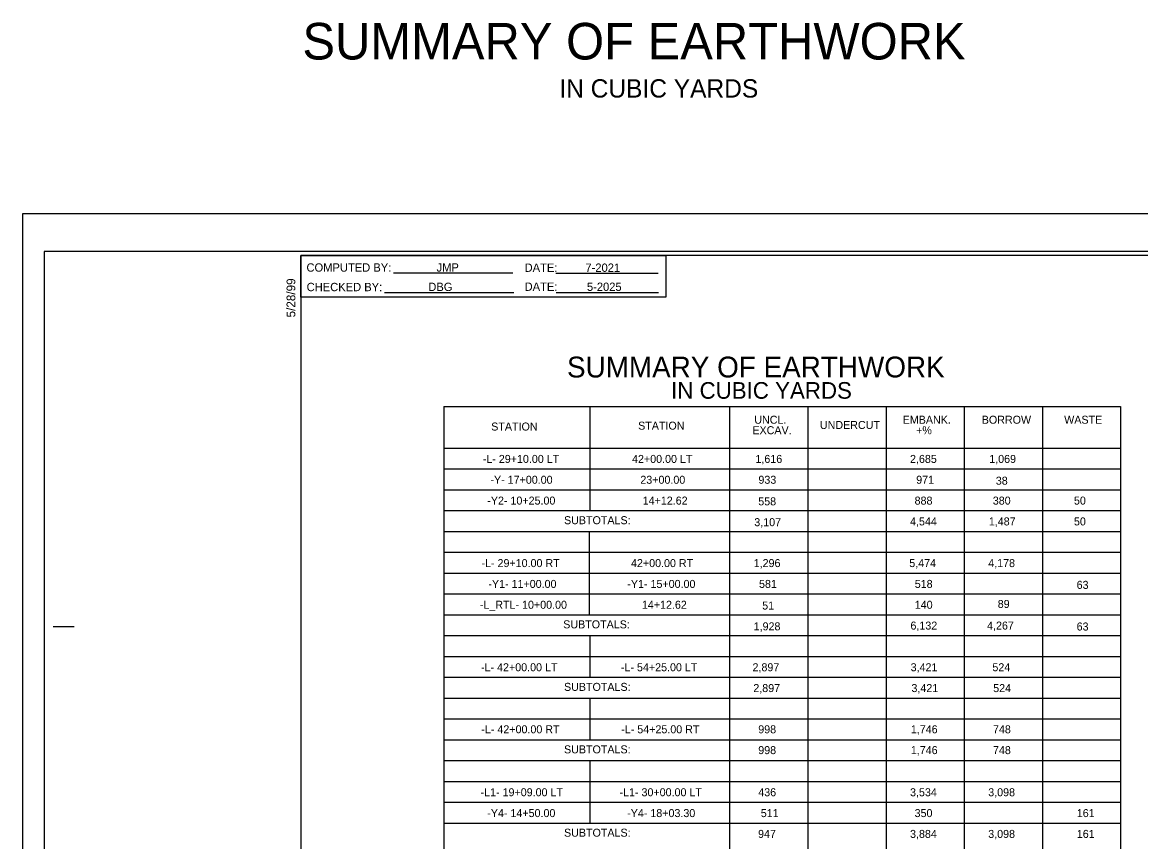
# Model space of a CAD drawing. Extents: x 1729625 to 1732014, y 538843 to 541329.
# Drawn here: x 1729815 to 1730486, y 540638 to 541130 of the extents above; entities that cross this region are included whole.
import ezdxf

# ---------------------------------------------------------------- set-up
doc = ezdxf.new("R2010")
doc.units = 0
for name, color, linetype in [('Old_Level_2', 7, 'Continuous'), ('Prop EOT', 7, 'Continuous'), ('Prop Horizontal Alignment', 7, 'Continuous'), ('Sheet Cutting Line CELL', 7, 'Continuous'), ('Sheet Data Field CELL', 7, 'Continuous'), ('Sheet Plot Border Inside CELL', 7, 'Continuous'), ('Sheet Plot Border Outside CELL', 7, 'Continuous'), ('Sheet Summary CELL', 7, 'Continuous')]:
    doc.layers.add(name, color=color, linetype=linetype)

msp = doc.modelspace()

# ---------------------------------------------------------------- linework, layer by layer
at = {"layer": 'Old_Level_2'}
for p, q in [((1730038.12, 540979.51), (1730109.67, 540979.51)), ((1730135.47, 540979.36), (1730196.87, 540979.36)), ((1730032.67, 540967.81), (1730110.37, 540967.81)), ((1730135.62, 540967.86), (1730197.02, 540967.86))]:
    msp.add_line(p, q, dxfattribs=at)
msp.add_lwpolyline([(1729982.47, 540989.91), (1730201.47, 540989.91), (1730201.47, 540964.91), (1729982.47, 540964.91)], close=True, dxfattribs=at)
at = {"layer": 'Prop EOT'}
for p, q in [((1730068.38, 540899.44), (1730474.29, 540899.44)), ((1730068.38, 540899.44), (1730068.38, 540361.94)), ((1730155.91, 540899.44), (1730155.91, 540836.94)), ((1730239.79, 540899.44), (1730239.79, 540361.94)), ((1730286.69, 540899.44), (1730286.69, 540361.94)), ((1730333.59, 540899.44), (1730333.59, 540361.94)), ((1730380.49, 540899.44), (1730380.49, 540361.94)), ((1730427.39, 540899.44), (1730427.39, 540361.94)), ((1730474.29, 540899.44), (1730474.29, 540361.94)), ((1730068.38, 540874.44), (1730474.29, 540874.44)), ((1730068.38, 540861.94), (1730474.29, 540861.94)), ((1730068.38, 540849.44), (1730474.29, 540849.44)), ((1730068.38, 540836.94), (1730474.29, 540836.94)), ((1730068.38, 540824.44), (1730474.29, 540824.44)), ((1730155.43, 540824.44), (1730155.43, 540774.44)), ((1730068.38, 540811.94), (1730474.29, 540811.94)), ((1730068.38, 540799.44), (1730474.29, 540799.44)), ((1730068.38, 540786.94), (1730474.29, 540786.94)), ((1730068.38, 540774.44), (1730474.29, 540774.44)), ((1730068.38, 540761.94), (1730474.29, 540761.94)), ((1730155.91, 540761.94), (1730155.91, 540736.94)), ((1730068.38, 540749.44), (1730474.29, 540749.44)), ((1730068.38, 540736.94), (1730474.29, 540736.94)), ((1730068.38, 540724.44), (1730474.29, 540724.44)), ((1730155.91, 540724.44), (1730155.91, 540699.44)), ((1730068.38, 540711.94), (1730474.29, 540711.94)), ((1730068.38, 540699.44), (1730474.29, 540699.44)), ((1730068.38, 540686.94), (1730474.29, 540686.94)), ((1730155.91, 540686.94), (1730155.91, 540649.44)), ((1730068.38, 540674.44), (1730474.29, 540674.44)), ((1730068.38, 540661.94), (1730474.29, 540661.94)), ((1730068.38, 540649.44), (1730474.29, 540649.44))]:
    msp.add_line(p, q, dxfattribs=at)
at = {"layer": 'Prop Horizontal Alignment'}
for p, q in [((1730193.49, 540868.01), (1730193.49, 540868.01)), ((1730199.74, 540867.91), (1730199.74, 540867.91)), ((1730208.79, 540868.11), (1730208.79, 540868.11)), ((1730214.39, 540868.01), (1730214.39, 540868.01))]:
    msp.add_line(p, q, dxfattribs=at)
at = {"layer": 'Sheet Cutting Line CELL'}
for p, q in [((1731499.47, 541014.91), (1729815.47, 541014.91)), ((1729815.47, 541014.91), (1729815.47, 539914.91))]:
    msp.add_line(p, q, dxfattribs=at)
at = {"layer": 'Sheet Plot Border Inside CELL'}
msp.add_lwpolyline([(1731494.97, 540992.46), (1729828.47, 540992.46), (1729828.47, 539937.36), (1731494.97, 539937.36)], close=True, dxfattribs=at)
at = {"layer": 'Sheet Plot Border Outside CELL'}
msp.add_lwpolyline([(1731499.47, 541014.91), (1729815.47, 541014.91), (1729815.47, 539914.91), (1731499.47, 539914.91)], close=True, dxfattribs=at)
at = {"layer": 'Sheet Summary CELL'}
for p, q in [((1729982.47, 540989.91), (1729982.47, 540949.46)), ((1729833.97, 540767.41), (1729846.47, 540767.41))]:
    msp.add_line(p, q, dxfattribs=at)
msp.add_lwpolyline([(1731482.47, 540989.91), (1729982.47, 540989.91), (1729982.47, 539939.91), (1731482.47, 539939.91)], close=True, dxfattribs=at)

# ---------------------------------------------------------------- texts
at = {"layer": 'Old_Level_2'}
for s, height, p in [('COMPUTED BY:', 4.9998, (1729985.92, 540980.26)), ('DATE:', 5, (1730116.77, 540980.16)), ('CHECKED BY:', 4.9998, (1729986.02, 540968.56)), ('DATE:', 5, (1730116.77, 540968.76))]:
    msp.add_text(s, height=height, dxfattribs=at).set_placement(p)
at = {"layer": 'Prop Horizontal Alignment'}
for s, height, p in [('SUMMARY OF EARTHWORK', 12.5001, (1730142.2, 540916.78)), ('IN CUBIC YARDS', 10, (1730204.66, 540904))]:
    msp.add_text(s, height=height, rotation=0.01193, dxfattribs=at).set_placement(p)
for s, p in [('UNCL.', (1730254.58, 540889.03)), ('EMBANK.', (1730343.59, 540889.03)), ('BORROW', (1730391.04, 540889.03)), ('WASTE', (1730440.49, 540889.03)), ('STATION', (1730096.74, 540884.94)), ('STATION', (1730184.88, 540885.47)), ('EXCAV.', (1730253.43, 540882.73)), ('UNDERCUT', (1730293.94, 540885.88)), ('+%', (1730351.65, 540882.73)), ('-L- 29+10.00 LT', (1730091.69, 540865.51)), ('42+00.00 LT', (1730181.23, 540865.51)), ('1,616', (1730255.26, 540865.51)), ('2,685', (1730348, 540865.51)), ('1,069', (1730395.53, 540865.51)), ('-Y- 17+00.00', (1730096.28, 540853.01)), ('23+00.00', (1730186.21, 540853.01)), ('933', (1730257.05, 540853.01)), ('971', (1730351.7, 540853.01)), ('38', (1730399.47, 540852.45)), ('-Y2- 10+25.00', (1730094.38, 540840.51)), ('14+12.62', (1730187.62, 540840.51)), ('558', (1730256.95, 540840.05)), ('888', (1730350.75, 540840.51)), ('380', (1730397.66, 540840.51)), ('50', (1730446.36, 540840.51)), ('SUBTOTALS:', (1730140.42, 540828.74)), ('3,107', (1730254.57, 540827.55)), ('4,544', (1730348.03, 540828.01)), ('1,487', (1730395.28, 540828.01)), ('50', (1730446.36, 540828.01)), ('-L- 29+10.00 RT', (1730090.91, 540803.01)), ('42+00.00 RT', (1730180.61, 540803.01)), ('1,296', (1730254.21, 540803.01)), ('5,474', (1730347.56, 540803.01)), ('4,178', (1730394.92, 540803.01)), ('-Y1- 11+00.00', (1730095.05, 540790.51)), ('-Y1- 15+00.00', (1730178.41, 540790.51)), ('581', (1730257.42, 540790.51)), ('518', (1730350.85, 540790.51)), ('63', (1730447.96, 540789.95)), ('-L_RTL- 10+00.00', (1730089.92, 540778.01)), ('14+12.62', (1730187.14, 540778.01)), ('51', (1730259.32, 540777.55)), ('140', (1730350.85, 540778.01)), ('89', (1730400.62, 540778.5)), ('SUBTOTALS:', (1730139.95, 540766.24)), ('1,928', (1730254.2, 540765.05)), ('6,132', (1730348.26, 540765.51)), ('4,267', (1730394.23, 540765.51)), ('63', (1730447.96, 540764.95)), ('-L- 42+00.00 LT', (1730090.64, 540740.51)), ('-L- 54+25.00 LT', (1730174.57, 540740.51)), ('2,897', (1730253.51, 540740.51)), ('3,421', (1730348.37, 540740.51)), ('524', (1730397.42, 540740.51)), ('SUBTOTALS:', (1730140.42, 540728.74)), ('2,897', (1730253.99, 540728.01)), ('3,421', (1730348.85, 540728.01)), ('524', (1730397.9, 540728.01)), ('-L- 42+00.00 RT', (1730090.83, 540703.29)), ('-L- 54+25.00 RT', (1730174.76, 540703.29)), ('998', (1730256.95, 540703.29)), ('1,746', (1730348.49, 540703.29)), ('748', (1730397.77, 540703.29)), ('SUBTOTALS:', (1730140.42, 540691.24)), ('998', (1730256.95, 540690.79)), ('1,746', (1730348.49, 540690.79)), ('748', (1730397.77, 540690.79)), ('-L1- 19+09.00 LT', (1730090.37, 540665.51)), ('-L1- 30+00.00 LT', (1730173.72, 540665.51)), ('436', (1730256.96, 540665.51)), ('3,534', (1730348.03, 540665.51)), ('3,098', (1730394.92, 540665.51)), ('-Y4- 14+50.00', (1730094.38, 540653.01)), ('-Y4- 18+03.30', (1730178.31, 540653.01)), ('511', (1730258.47, 540653.01)), ('350', (1730350.75, 540653.01)), ('161', (1730448.06, 540653.01)), ('SUBTOTALS:', (1730140.42, 540641.24)), ('947', (1730256.84, 540640.51)), ('3,884', (1730348.03, 540640.51)), ('3,098', (1730394.92, 540640.51)), ('161', (1730448.06, 540640.51))]:
    msp.add_text(s, height=4.8, dxfattribs=at).set_placement(p)
at = {"layer": 'Sheet Data Field CELL'}
for s, p in [('JMP', (1730063.96, 540980.31)), ('7-2021', (1730153.27, 540980.16)), ('DBG', (1730059.01, 540968.66)), ('5-2025', (1730154.17, 540968.71))]:
    msp.add_text(s, height=5, dxfattribs=at).set_placement(p)
at = {"layer": 'Sheet Summary CELL'}
for s, height, p in [('SUMMARY OF EARTHWORK', 21.9501, (1729983.47, 541107.58)), ('IN CUBIC YARDS', 10.9998, (1730137.62, 541084.73))]:
    msp.add_text(s, height=height, dxfattribs=at).set_placement(p)
msp.add_text('5/28/99', height=5.25, rotation=90, dxfattribs=at).set_placement((1729979.22, 540952.81))

doc.saveas('drawing.dxf')
